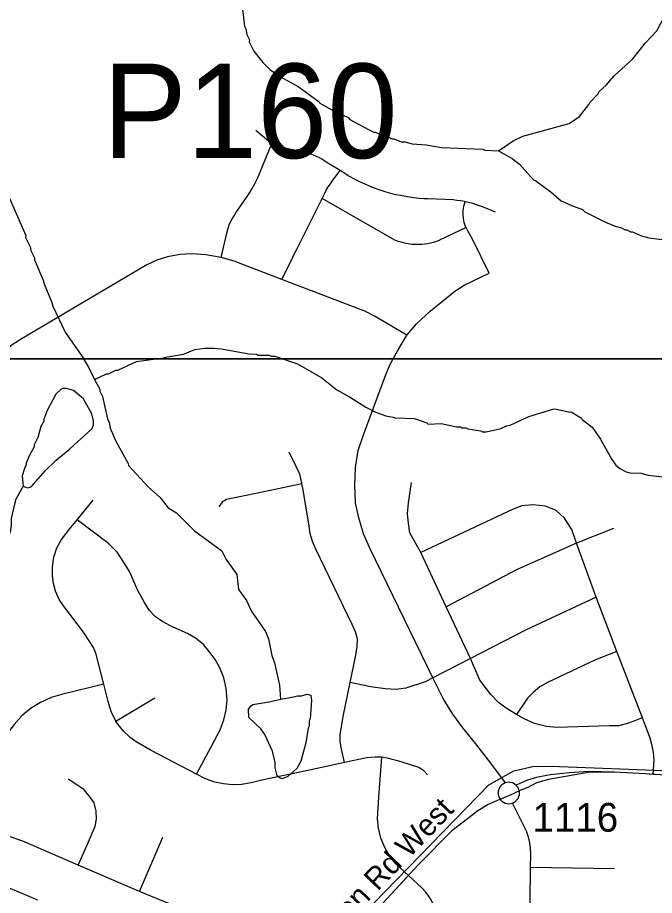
# Model space of a CAD drawing. Extents: x 1383679 to 1536984, y 460658 to 651027.
# Drawn here: x 1405924 to 1408689, y 518428 to 522240 of the extents above; entities that cross this region are included whole.
import ezdxf

# ---------------------------------------------------------------- set-up
doc = ezdxf.new("R2010")
doc.units = 0
for name, color, linetype in [('Default', 7, 'Continuous'), ('Exist Boundary Political City Limit New', 7, 'Continuous'), ('Exist Hydrographic Misc Water Feature', 7, 'Continuous'), ('Exist Road Non-System Type 51', 7, 'Continuous'), ('Exist Road Secondary Structure Pipe Number Label', 7, 'Continuous'), ('Exist Road Secondary Type 51 Attributed', 7, 'Continuous'), ('Exist Road Secondary Type 51 Label', 7, 'Continuous'), ('Exist Road Secondary Type 51 Number Label', 7, 'Continuous'), ('Map Preparation Boundary City Limit Buffer Line', 7, 'Continuous'), ('Map Preparation Inset Cut Line', 7, 'Continuous')]:
    doc.layers.add(name, color=color, linetype=linetype)

msp = doc.modelspace()

# ---------------------------------------------------------------- linework, layer by layer
at = {"layer": 'Default'}
msp.add_lwpolyline([(1406919, 517827.2), (1407970.4, 518907.8), (1408078.6, 518968.6), (1408160.1, 518986.8), (1408239.2, 518989.2), (1408764.1, 518968.8)], dxfattribs=at)
at = {"layer": 'Exist Boundary Political City Limit New'}
msp.add_lwpolyline([(1406919, 517827.2), (1407970.4, 518907.8), (1408078.6, 518968.6), (1408160.1, 518986.8), (1408239.2, 518989.2), (1408764.1, 518968.8)], dxfattribs=at)
at = {"layer": 'Exist Hydrographic Misc Water Feature'}
for points in [[(1408011.7, 521660.3), (1408075.1, 521704.9), (1408117.6, 521723.9), (1408318.7, 521779.4), (1408363.4, 521810.3), (1408404.5, 521861.4), (1408408.7, 521871.3), (1408443.6, 521908.5), (1408447.8, 521916.4), (1408480.4, 521947.7), (1408513.3, 521986.9), (1408594.9, 522061.1), (1408649.4, 522130.3), (1408699.6, 522182.7), (1408751.8, 522285.4), (1408838, 522387.5), (1409020.3, 522579.2), (1409049.3, 522626.6), (1409127.1, 522710.8), (1409210, 522842.9), (1409276.6, 522961.3)], [(1406901.2, 522275), (1406909.6, 522202.9), (1406915.3, 522190.8), (1406918.8, 522166.7), (1406930.3, 522142.4), (1406930.2, 522134.4), (1406949.3, 522094), (1406988.2, 522045.2), (1407019.6, 522014.5), (1407062.9, 521983.5), (1407142, 521939.8), (1407233.9, 521873.4), (1407236.5, 521867.7), (1407287.8, 521838.5), (1407359.1, 521805), (1407367, 521796.8), (1407469.8, 521742.5), (1407477.8, 521742.3), (1407501.5, 521729.8), (1407533.4, 521721.1), (1407549.2, 521712.7), (1407557.2, 521712.5), (1407588.8, 521699.8), (1407604.8, 521699.5), (1407636.7, 521690.7), (1407698.2, 521686.9), (1407764.4, 521675.9), (1407944.3, 521667.8), (1407952.2, 521663.7), (1408011.7, 521660.3)], [(1408011.7, 521660.3), (1408071.4, 521627), (1408102.9, 521602.3), (1408163.4, 521535), (1408173.3, 521530.8), (1408240.3, 521481.3), (1408283.5, 521444.3), (1408332.3, 521421.4), (1408376.7, 521406.2), (1408386.5, 521396), (1408473.5, 521352.1), (1408513.2, 521335.2), (1408545, 521326.5), (1408560.8, 521318.2), (1408568.8, 521318), (1408584.7, 521309.6), (1408592.7, 521309.4), (1408632.3, 521292.5), (1408664.1, 521283.8), (1408767.8, 521269.5)], [(1405814.8, 521623.7), (1405959.7, 521292.6), (1405959.5, 521284.6), (1405978.7, 521244.2), (1405982.4, 521228.1), (1405997.6, 521195.8), (1405997.4, 521187.9), (1406035.6, 521099), (1406039.2, 521082.9), (1406073.4, 521002.2), (1406077.1, 520986.1), (1406130.6, 520873), (1406204.3, 520767.3), (1406233.3, 520718.7), (1406258.6, 520668.4)], [(1406258.6, 520668.4), (1406310.8, 520693), (1406318.8, 520692.8), (1406351.1, 520708.1), (1406359.1, 520707.9), (1406439.9, 520746.1), (1406524.2, 520758.2), (1406532.2, 520756), (1406574.5, 520766.7), (1406644.7, 520777.4), (1406693.2, 520798.4), (1406737.3, 520803.4), (1406777.3, 520804.5), (1406809.2, 520801.7), (1406928.8, 520779.1), (1406960.8, 520778.4), (1406968.7, 520774.2), (1407016.6, 520773.1), (1407024.5, 520768.9), (1407040.5, 520768.6), (1407139, 520736.7), (1407244.5, 520674.8), (1407309.5, 520622.6), (1407364.8, 520593.4), (1407435.9, 520547.8), (1407475.4, 520526.9), (1407523.1, 520509.8), (1407555, 520505.1), (1407562.9, 520500.9), (1407646.9, 520499), (1407701.3, 520479.3), (1407706.3, 520473.7), (1407762.4, 520476.5), (1407830.1, 520462.9), (1407846.1, 520462.6), (1407854.1, 520458.4), (1407870.1, 520458.1), (1407878, 520453.9), (1407933.7, 520444.6), (1407941.6, 520440.4), (1407957.6, 520440.1), (1408022, 520454.6), (1408046.2, 520466.1), (1408062.3, 520469.7), (1408143.2, 520507.9), (1408247.9, 520539.5), (1408255.9, 520541.3), (1408323.2, 520526.1), (1408327.6, 520527.7), (1408372.3, 520499.4), (1408374.9, 520494.7), (1408418.2, 520461.7), (1408455.1, 520408.9), (1408503.2, 520319.9), (1408520.6, 520295.5), (1408538.3, 520281.1), (1408566, 520266.5), (1408581.9, 520262.1), (1408629.9, 520261.1), (1408661.8, 520252.4), (1408785.4, 520237.6)], [(1406258.6, 520668.4), (1406281.3, 520625.7), (1406281.1, 520617.7), (1406292.6, 520593.5), (1406314.5, 520497), (1406322.2, 520480.8), (1406325.6, 520456.8), (1406350.4, 520400.2), (1406404.4, 520303.1), (1406406.2, 520295.1), (1406492.1, 520201.1), (1406543.2, 520156), (1406578.2, 520111.2), (1406613.7, 520088.5), (1406692, 520010.8), (1406810.3, 519924.1), (1406829.4, 519885.7), (1406876, 519820.7), (1406882.6, 519756.5), (1406917.6, 519707.8), (1406938.6, 519663.3), (1407000.7, 519574), (1407014, 519541.7), (1407028.4, 519469.4), (1407039.7, 519437.2), (1407061.7, 519340.7), (1407065.4, 519279.9)], [(1406211.2, 520584.4), (1406167.2, 520620.3), (1406137.4, 520628.9), (1406121.4, 520629.3), (1406113.3, 520625.5), (1406090.8, 520604), (1406053.2, 520532.9), (1406038.4, 520495.2), (1406038.2, 520487.2), (1406025.7, 520463.5), (1406012.7, 520415.8), (1405996, 520384.2), (1405995.9, 520376.2), (1405975, 520336.7), (1405962.3, 520305), (1405962.2, 520297), (1405953.8, 520281.2), (1405945, 520249.4), (1405949.3, 520205.1)], [(1405949.3, 520205.1), (1405960, 520201.1), (1405967.9, 520196.9), (1405984.1, 520202.6), (1406043.6, 520271.2), (1406092.6, 520318.1), (1406151.6, 520366.7), (1406247.6, 520454.5), (1406254, 520470.4), (1406254.3, 520486.4), (1406247, 520518.5), (1406211.2, 520584.4)], [(1405949.3, 520205.1), (1405916.8, 520148.1), (1405910.4, 520126.2), (1405897.1, 520064.6), (1405896.3, 520030.6), (1405891.8, 520006.7), (1405874.6, 519951.1), (1405857.9, 519919.6), (1405832.5, 519854.4), (1405796.5, 519800.1), (1405791.3, 519797.1), (1405766.2, 519749.7), (1405758.8, 519589.9), (1405754.4, 519576), (1405753.9, 519550.1), (1405749.7, 519542.1), (1405749.3, 519526.2), (1405736.3, 519478.4), (1405728, 519462.6), (1405719.1, 519422.9), (1405710.8, 519407.1), (1405694.8, 519348.7)], [(1407065.4, 519279.9), (1407092.4, 519284), (1407140.7, 519295), (1407156.7, 519294.6), (1407180.8, 519302), (1407196.7, 519297.7), (1407200.2, 519273.6), (1407194.4, 519193.8), (1407190.3, 519185.9), (1407189.8, 519161.9), (1407185.6, 519154), (1407176.2, 519090.3), (1407154.5, 519010.8), (1407135.8, 518979.2), (1407097, 518944.1), (1407072.8, 518934.6), (1407064.8, 518936.8), (1407051.1, 518947.1), (1407041.9, 518981.3), (1407042.4, 519005.3), (1407031.4, 519053.5), (1406997, 519126.3), (1406979.5, 519150.7), (1406928.6, 519199.8), (1406927.3, 519235.8), (1406937.7, 519251.5), (1406945.8, 519257.4), (1407024, 519269.6), (1407065.4, 519279.9)]]:
    msp.add_lwpolyline(points, dxfattribs=at)
at = {"layer": 'Exist Road Non-System Type 51'}
for p, q in [((1406183.1, 520059.3), (1406252.6, 520143.7)), ((1408511.4, 520020.7), (1408350.2, 519956.7)), ((1408434.9, 519723.3), (1408350.2, 519956.7)), ((1407785.1, 519681.2), (1407675, 519917.4)), ((1408525.8, 519486.7), (1408434.9, 519723.3)), ((1407889.8, 519456.9), (1407785.1, 519681.2)), ((1408636.1, 519199.2), (1408525.8, 519486.7)), ((1407889.8, 519456.9), (1407726.4, 519372.2)), ((1406350.6, 519185), (1406520.1, 519286.1)), ((1406454.2, 518445.1), (1406554.4, 518680)), ((1406454.2, 518445.1), (1406187.5, 518559.6)), ((1408515.4, 518543.2), (1408150.9, 518549.4))]:
    msp.add_line(p, q, dxfattribs=at)
for points in [[(1407027.9, 521693.4), (1407013.2, 521702.5), (1406959.1, 521749.6)], [(1406808.5, 521197.4), (1406832.2, 521304.1), (1406838.1, 521324.8), (1406843.2, 521339.7), (1406849.1, 521352.6), (1406856.1, 521365.5), (1406863.9, 521378.5), (1406872.4, 521391.4), (1406920.9, 521461.9), (1406932.5, 521480), (1406942.2, 521496.8), (1406953.9, 521517.6), (1406965.5, 521541.5), (1407027.9, 521693.4)], [(1407324.1, 521574.9), (1407288.1, 521597.6), (1407264.4, 521612.3), (1407248, 521623), (1407234.9, 521629.9), (1407222.2, 521636.1), (1407209.1, 521642.2), (1407194.8, 521647.2), (1407177.1, 521652.5), (1407161.1, 521656.2), (1407086.1, 521672.6), (1407068.9, 521677.1), (1407049.6, 521683.6), (1407031.2, 521691.4), (1407027.9, 521693.4)], [(1407245.9, 521453.4), (1407256.6, 521474.8), (1407264.4, 521490.4), (1407272.9, 521504.6), (1407281.9, 521518.2), (1407292.1, 521533.1), (1407324.1, 521574.9)], [(1407867.2, 521439.8), (1407864.4, 521440.6), (1407848, 521443.5), (1407831.6, 521445.9), (1407815.6, 521447.6), (1407706.6, 521452.1), (1407688.1, 521452.9), (1407666.9, 521454.5), (1407644.8, 521457.4), (1407616.9, 521461.1), (1407586.1, 521466.4), (1407566.5, 521470.1), (1407544.8, 521475.4), (1407524.2, 521481.6), (1407502.1, 521489), (1407469.8, 521500.4), (1407448.4, 521508.7), (1407425.9, 521518.5), (1407409.5, 521526.7), (1407390.2, 521536.5), (1407361.6, 521551.2), (1407324.1, 521574.9)], [(1407071, 521102.6), (1407119.5, 521199.9), (1407125.4, 521212.2), (1407134.4, 521231), (1407245.9, 521453.4)], [(1407870.9, 521328.5), (1407756.1, 521272.3), (1407743.1, 521267.8), (1407728.2, 521263.3), (1407715.9, 521260.1), (1407703.6, 521257.5), (1407691.4, 521256.2), (1407678.4, 521254.9), (1407664.9, 521254.2), (1407651.2, 521254.2), (1407637, 521254.9), (1407619.6, 521257.5), (1407604, 521260.1), (1407589.1, 521264), (1407576.2, 521267.8), (1407562, 521273.7), (1407245.9, 521453.4)], [(1407870.9, 521328.5), (1407869.1, 521332.2), (1407863, 521350.4), (1407860.1, 521367.8), (1407858.4, 521386.4), (1407858.9, 521403.8), (1407861.4, 521421.1), (1407867.2, 521439.8)], [(1407999.2, 521394.3), (1407942.2, 521417.2), (1407920.1, 521425), (1407899.6, 521431.6), (1407880.8, 521436.5), (1407867.2, 521439.8)], [(1407971.8, 521130.3), (1407900.2, 521273.9), (1407878.2, 521313.2), (1407870.9, 521328.5)], [(1406808.5, 521197.4), (1406799.9, 521199.9), (1406741.9, 521209.2), (1406681.6, 521213.8), (1406629.4, 521210.3), (1406574.9, 521201.1), (1406528.4, 521186), (1406485, 521166.4), (1405937.6, 520841.2), (1405896.9, 520816.1), (1405853.1, 520778.6), (1405803.1, 520737.9), (1405756.1, 520691), (1405721.8, 520650.3), (1405579.2, 520443.9)], [(1407071, 521102.6), (1406863.8, 521181.3), (1406808.5, 521197.4)], [(1407613.9, 520859.8), (1407615.1, 520862), (1407656.4, 520909.2), (1407715.4, 520965.3), (1407821.8, 521051), (1407863, 521077.5), (1407971.8, 521130.3)], [(1407613.9, 520859.8), (1407476.4, 520941.8), (1407432, 520965.3), (1407071, 521102.6)], [(1407726.4, 519372.2), (1407452.6, 519935.1), (1407426.1, 519997.1), (1407405.5, 520067.9), (1407390.6, 520132.8), (1407387.8, 520209.6), (1407390.6, 520286.3), (1407402.5, 520360.2), (1407426.1, 520428.1), (1407520.6, 520684.9), (1407541.2, 520735.1), (1407576.6, 520797.1), (1407613.9, 520859.8)], [(1407158.4, 520214.9), (1407157.8, 520219), (1407149.4, 520256.2), (1407133.6, 520290.9), (1407102.6, 520353.1)], [(1407158.4, 520214.9), (1406966.1, 520174.8), (1406830.9, 520147.2), (1406811.8, 520135.2), (1406798.6, 520114.9)], [(1407368.2, 519352.2), (1407392.4, 519470.9), (1407398.4, 519508), (1407399.4, 519541.6), (1407391.1, 519572.7), (1407376.8, 519603.8), (1407218.6, 519930.6), (1407204.4, 519964), (1407194.8, 519998.8), (1407188.9, 520041.8), (1407163.6, 520186.7), (1407158.4, 520214.9)], [(1407675, 519917.4), (1407627.5, 520002.1), (1407621.4, 520043.4), (1407617.1, 520084.7), (1407621.4, 520132.2), (1407633.8, 520221)], [(1408350.2, 519956.7), (1408329.6, 520016.6), (1408298.6, 520066.1), (1408261.5, 520099.2), (1408216, 520117.8), (1408160.2, 520123.9), (1408112.8, 520119.8), (1408075.6, 520105.3), (1407675, 519917.4)], [(1406298.6, 519344.4), (1406264.5, 519479.8), (1406254, 519504.8), (1406235.6, 519533.7), (1406210.5, 519570.7), (1406123.6, 519685.2), (1406105.2, 519712.9), (1406089.4, 519748.5), (1406080.1, 519781.5), (1406076.1, 519815.7), (1406076.1, 519853.9), (1406081.4, 519896.1), (1406094.6, 519936.8), (1406114.4, 519972.5), (1406155.1, 520025.2), (1406183.1, 520059.3)], [(1406701.6, 518954.4), (1406765.1, 519072.7), (1406803.4, 519146.4), (1406819.1, 519189.9), (1406829.8, 519233.3), (1406833.6, 519276.8), (1406829.8, 519326.9), (1406819.1, 519373), (1406802.1, 519416.5), (1406782.4, 519452.1), (1406755.9, 519486.3), (1406730.9, 519516.6), (1406696.6, 519544.2), (1406662.4, 519565.3), (1406599.1, 519593), (1406554.4, 519615.4), (1406521.4, 519639.2), (1406495.1, 519666.8), (1406475.4, 519699.8), (1406446.4, 519751.2), (1406409.5, 519834.2), (1406387.1, 519872.3), (1406356.8, 519918.4), (1406318.6, 519955.3), (1406183.1, 520059.3)], [(1408350.2, 519956.7), (1408092.1, 519843.1), (1407785.1, 519681.2)], [(1408434.9, 519723.3), (1408129.4, 519578.8), (1407889.8, 519456.9)], [(1408525.8, 519486.7), (1408432.9, 519450.8), (1408224.2, 519351.7), (1408191.2, 519333.1), (1408162.4, 519308.2), (1408137.6, 519283.5), (1408089.9, 519214)], [(1408089.9, 519214), (1408044.6, 519240.2), (1408011.6, 519264.9), (1407978.6, 519300), (1407931.1, 519362), (1407889.8, 519456.9)], [(1407726.4, 519372.2), (1407692.8, 519354.8), (1407609, 519327.2), (1407568.2, 519322.5), (1407520.4, 519324.9), (1407458.1, 519333.2), (1407368.2, 519352.2)], [(1408041.6, 518916.5), (1407978.1, 519002.2), (1407907.4, 519093.8), (1407857.1, 519155.8), (1407812.9, 519214.8), (1407771.5, 519282.7), (1407726.4, 519372.2)], [(1406298.6, 519344.4), (1406120.9, 519301.9), (1406070.9, 519287.4), (1406023.4, 519265), (1405981.2, 519238.7), (1405943.1, 519207), (1405908.9, 519170.2), (1405879.9, 519130.6), (1405853.5, 519087.2), (1405836.4, 519039.7), (1405824.5, 518987), (1405817.9, 518934.3), (1405815.2, 518889.5), (1405816.6, 518822.3), (1405817.9, 518764.3), (1405817.9, 518731.4), (1405815.2, 518705.1)], [(1406350.6, 519185), (1406330.4, 519226.8), (1406317.2, 519270.2), (1406298.6, 519344.4)], [(1407343.8, 519004.3), (1407330.1, 519062.8), (1407324.1, 519096.2), (1407325.2, 519126.2), (1407339.6, 519211.2), (1407368.2, 519352.2)], [(1408636.1, 519199.2), (1408575.4, 519176.1), (1408534, 519163.8), (1408492.8, 519163.8), (1408265.6, 519157.5), (1408220.1, 519161.7), (1408168.5, 519174.1), (1408123.1, 519194.7), (1408089.9, 519214)], [(1406701.6, 518954.4), (1406504.4, 519056.9), (1406438.5, 519095.1), (1406413.5, 519113.5), (1406383, 519142.5), (1406351.5, 519183.3), (1406350.6, 519185)], [(1408682.5, 518953.4), (1408686.9, 519015.1), (1408684.8, 519048.1), (1408678.6, 519077), (1408670.4, 519110), (1408649.6, 519163.8), (1408636.1, 519199.2)], [(1407505.6, 519027.8), (1407476.6, 519027.8), (1407439.8, 519025.2), (1407343.8, 519004.3)], [(1407621.1, 518514.4), (1407566, 518565.2), (1407538.2, 518599.7), (1407518.6, 518635.6), (1407500.6, 518676.5), (1407490.9, 518719), (1407485.9, 518759.9), (1407492.4, 518854.8), (1407505.6, 519027.8)], [(1407703.1, 518951.4), (1407687.4, 518968.6), (1407666.4, 518983.1), (1407589.9, 519008.1), (1407535.9, 519022.6), (1407505.6, 519027.8)], [(1407343.8, 519004.3), (1407192, 518971.2), (1406983.9, 518927.7), (1406937.8, 518917.2), (1406896.9, 518909.2), (1406856.1, 518908), (1406817.9, 518911.9), (1406781, 518919.8), (1406740.1, 518934.3), (1406701.6, 518954.4)], [(1408682.5, 518953.4), (1408647.6, 518955.5), (1408515.4, 518962.3), (1408403.8, 518966.3), (1408318.9, 518960.4), (1408236.6, 518951.4), (1408177, 518939.2), (1408137.9, 518928.6), (1408114.2, 518918), (1408088.9, 518905.7)], [(1408927.9, 518947.1), (1408907, 518945.8), (1408872.1, 518944.8), (1408839.8, 518944.8), (1408776.6, 518947.8), (1408682.5, 518953.4)], [(1406187.5, 518559.6), (1406227.6, 518649.8), (1406260.6, 518728.8), (1406267.1, 518759.1), (1406265.9, 518793.3), (1406256.6, 518830.2), (1406235.6, 518860.5), (1406211.9, 518886.9), (1406177.6, 518910.6), (1406143.4, 518933)], [(1408041.6, 518916.5), (1408040.6, 518916.1), (1408033.2, 518912.7), (1408026.6, 518908), (1408020.9, 518902.3), (1408016.2, 518895.7), (1408012.8, 518888.3), (1408010.8, 518880.5), (1408010, 518872.4), (1408010.8, 518864.4), (1408012.8, 518856.5), (1408015.6, 518850.3)], [(1408088.9, 518905.7), (1408086.2, 518908), (1408079.6, 518912.7), (1408072.4, 518916.1), (1408064.5, 518918.2), (1408056.4, 518918.9), (1408048.4, 518918.2), (1408041.6, 518916.5)], [(1408071.9, 518828.6), (1408072.4, 518828.8), (1408079.6, 518832.2), (1408086.4, 518836.8), (1408092, 518842.5), (1408096.8, 518849.2), (1408100.1, 518856.5), (1408102.2, 518864.3), (1408102.9, 518872.4), (1408102.2, 518880.5), (1408100.1, 518888.3), (1408096.8, 518895.7), (1408092, 518902.3), (1408088.9, 518905.7)], [(1408015.6, 518850.3), (1408020.5, 518843), (1408020.9, 518842.6), (1408026.6, 518836.8), (1408033.2, 518832.2), (1408040.6, 518828.8), (1408048.4, 518826.7), (1408056.5, 518825.9), (1408064.5, 518826.7), (1408071.9, 518828.6)], [(1408150.9, 518549.4), (1408151.6, 518607.4), (1408150.5, 518631.8), (1408147.5, 518655.3), (1408142.4, 518680.8), (1408133.2, 518707.2), (1408071.9, 518828.6)], [(1406187.5, 518559.6), (1405947, 518662.9), (1405854.9, 518695.8), (1405815.2, 518705.1)], [(1408131.8, 518107.4), (1408139.4, 518141.7), (1408144.4, 518169.2), (1408146.5, 518193.7), (1408147.5, 518221.2), (1408147.5, 518252.8), (1408150.9, 518549.4)], [(1407621.1, 518514.4), (1407528.1, 518413.8), (1407416.8, 518294.4), (1407275.1, 518148.8), (1407130.2, 518001.2), (1407076.1, 517946)], [(1407806.1, 518149.8), (1407806, 518152.7), (1407802.8, 518172.1), (1407796.2, 518194.8), (1407736.1, 518366.4), (1407728, 518389.1), (1407719.4, 518408.1), (1407708.6, 518425.9), (1407695, 518443.8), (1407680.9, 518459.5), (1407621.1, 518514.4)], [(1406013, 518406.5), (1405835.1, 518481.2)], [(1406704.6, 518371.8), (1406616.4, 518383.7), (1406588.6, 518390.2), (1406526.8, 518413.9), (1406454.2, 518445.1)]]:
    msp.add_lwpolyline(points, dxfattribs=at)
at = {"layer": 'Exist Road Secondary Type 51 Attributed'}
msp.add_lwpolyline([(1408690.1, 518953), (1408647.6, 518955.5), (1408515.4, 518962.3), (1408409.5, 518963.1), (1408228.6, 518930.8), (1408176.8, 518916.2), (1408139, 518896.8), (1408101.4, 518882.4), (1408074.9, 518868.6), (1407967.1, 518821.9), (1407917.9, 518792.5), (1407902.2, 518779.3), (1407809.5, 518708.6), (1407663.6, 518560.5), (1407528.2, 518413.7), (1407416.7, 518294.4), (1407275.1, 518148.8), (1407130.2, 518001.3), (1407076.1, 517946)], dxfattribs=at)
at = {"layer": 'Map Preparation Boundary City Limit Buffer Line'}
msp.add_lwpolyline([(1406919, 517827.2), (1407970.4, 518907.8), (1408078.6, 518968.6), (1408160.1, 518986.8), (1408239.2, 518989.2), (1408764.1, 518968.8)], dxfattribs=at)
msp.add_lwpolyline([(1406919, 517827.2), (1407970.4, 518907.8), (1408078.6, 518968.6), (1408160.1, 518986.8), (1408239.2, 518989.2), (1408764.1, 518968.8)], dxfattribs=at)
at = {"layer": 'Map Preparation Inset Cut Line'}
for points in [[(1458567.8, 520758.2), (1396051.8, 520758.2), (1396051.8, 564142.2), (1458567.8, 564142.2), (1458567.8, 520758.2)], [(1446195.4, 477316), (1383679.3, 477316), (1383679.3, 520758.2), (1458567.8, 520758.2), (1458567.8, 493672.2), (1446195.4, 493672.2), (1446195.4, 477316)]]:
    msp.add_lwpolyline(points, dxfattribs=at)

# ---------------------------------------------------------------- texts
at = {"layer": 'Exist Road Secondary Structure Pipe Number Label'}
msp.add_text('P160', height=410.1, dxfattribs=at).set_placement((1406293.1, 521629.4))
at = {"layer": 'Exist Road Secondary Type 51 Label'}
msp.add_text('Shopton Rd West', height=95, rotation=46.3442, dxfattribs=at).set_placement((1407136, 518075.3))
at = {"layer": 'Exist Road Secondary Type 51 Number Label'}
msp.add_text('1116', height=125, dxfattribs=at).set_placement((1408159.4, 518704.4))

doc.saveas('drawing.dxf')
